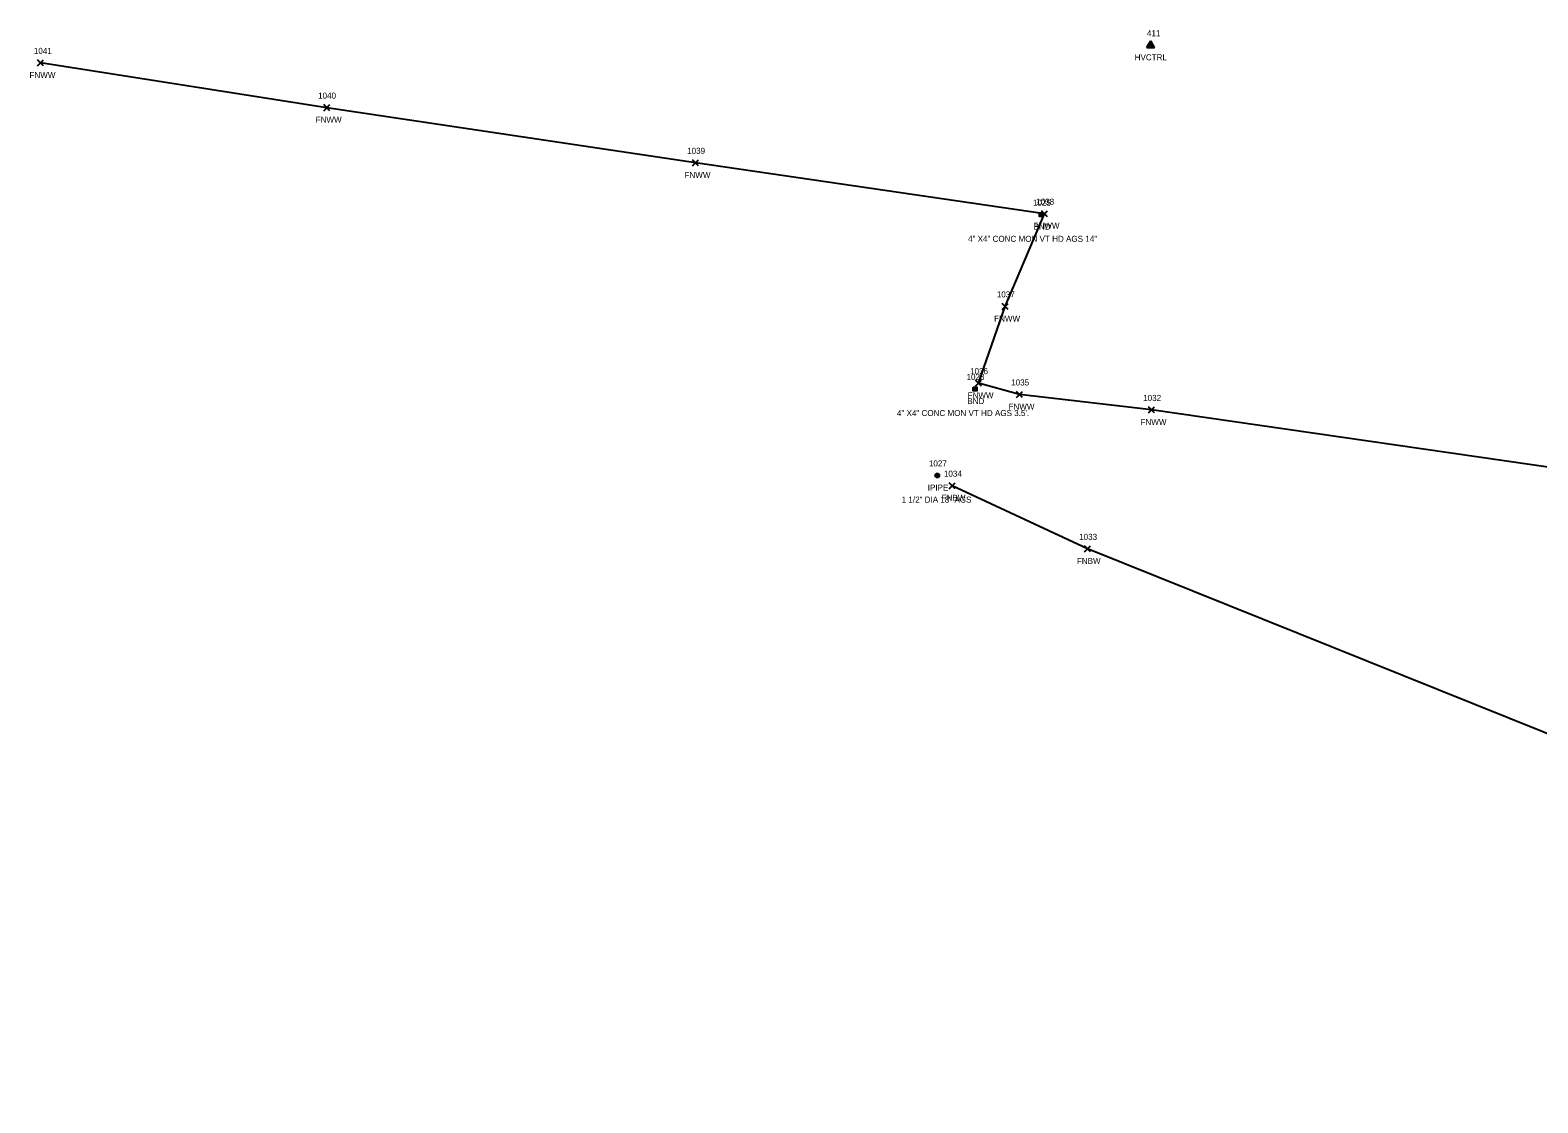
# Model space of a CAD drawing. Extents: x 1476446 to 1480467, y 706602 to 709082.
# Drawn here: x 1476446 to 1476946, y 707427 to 707782 of the extents above; entities that cross this region are included whole.
import ezdxf

# ---------------------------------------------------------------- set-up
doc = ezdxf.new("R2010")
doc.units = 0
for name, color, linetype in [('C_A', 7, 'Continuous'), ('C_I', 7, 'Continuous'), ('CPSM', 7, 'Continuous'), ('L_A', 7, 'Continuous'), ('L_I', 7, 'Continuous'), ('L_TIC', 7, 'Continuous'), ('Level 18', 7, 'Continuous'), ('LFNC', 7, 'Continuous'), ('M_A', 7, 'Continuous'), ('M_C', 7, 'Continuous'), ('M_I', 7, 'Continuous'), ('MPIP', 7, 'Continuous')]:
    doc.layers.add(name, color=color, linetype=linetype)

msp = doc.modelspace()

# ---------------------------------------------------------------- linework, layer by layer
at = {"layer": 'CPSM'}
for p, q in [((1476816.13, 707776.73), (1476817.38, 707778.9)), ((1476816.13, 707776.73), (1476817.38, 707777.45)), ((1476816.13, 707776.73), (1476818.63, 707776.73)), ((1476818.63, 707776.73), (1476817.38, 707778.9)), ((1476817.38, 707777.45), (1476817.38, 707778.9)), ((1476817.38, 707777.45), (1476817.38, 707777.45)), ((1476817.38, 707777.45), (1476818.63, 707776.73))]:
    msp.add_line(p, q, dxfattribs=at)
at = {"layer": 'L_TIC'}
for points in [[(1476447.98, 707770.58), (1476449.98, 707772.58)], [(1476449.98, 707770.58), (1476447.98, 707772.58)], [(1476542.95, 707755.73), (1476544.95, 707757.73)], [(1476544.95, 707755.73), (1476542.95, 707757.73)], [(1476665.34, 707737.41), (1476667.34, 707739.41)], [(1476667.34, 707737.41), (1476665.34, 707739.41)], [(1476781.16, 707720.55), (1476783.16, 707722.55)], [(1476783.16, 707720.55), (1476781.16, 707722.55)], [(1476768.09, 707689.76), (1476770.09, 707691.76)], [(1476770.09, 707689.76), (1476768.09, 707691.76)], [(1476759.27, 707664.31), (1476761.27, 707666.31)], [(1476761.27, 707664.31), (1476759.27, 707666.31)], [(1476772.86, 707660.56), (1476774.86, 707662.56)], [(1476774.86, 707660.56), (1476772.86, 707662.56)], [(1476816.67, 707655.43), (1476818.67, 707657.43)], [(1476818.67, 707655.43), (1476816.67, 707657.43)], [(1476750.54, 707630.28), (1476752.54, 707632.28)], [(1476752.54, 707630.28), (1476750.54, 707632.28)], [(1476795.42, 707609.33), (1476797.42, 707611.33)], [(1476797.42, 707609.33), (1476795.42, 707611.33)]]:
    msp.add_lwpolyline(points, dxfattribs=at)
at = {"layer": 'Level 18'}
for points in [[(1476780.46, 707721.85), (1476781.71, 707721.85), (1476781.71, 707720.6), (1476780.46, 707720.6)], [(1476758.43, 707664.03), (1476759.68, 707664.03), (1476759.68, 707662.78), (1476758.43, 707662.78)]]:
    msp.add_lwpolyline(points, close=True, dxfattribs=at)
for centre in [(1476781.08, 707721.22), (1476759.05, 707663.4)]:
    msp.add_circle(centre, 0.0833, dxfattribs=at)
at = {"layer": 'LFNC'}
for points in [[(1478416.61, 707432.38), (1478229.51, 707458.66), (1478087.28, 707476.81), (1477059.97, 707622.26), (1476970.61, 707634.31), (1476817.67, 707656.43), (1476773.86, 707661.56), (1476760.27, 707665.31), (1476769.09, 707690.76), (1476782.16, 707721.55), (1476666.34, 707738.41), (1476543.95, 707756.73), (1476448.98, 707771.58)], [(1479373.53, 706612.83), (1479179.17, 706689.1), (1478932.9, 706779.82), (1478858.54, 706807.19), (1478649.63, 706887.84), (1478518.06, 706938.91), (1478366.6, 707000.67), (1478164.37, 707075.29), (1476959.3, 707544.85), (1476796.42, 707610.33), (1476751.54, 707631.28)]]:
    msp.add_lwpolyline(points, dxfattribs=at)
at = {"layer": 'MPIP'}
msp.add_lwpolyline([(1476746.9, 707634.69), (1476746.56, 707635.02), (1476746.23, 707634.69), (1476746.56, 707634.36)], close=True, dxfattribs=at)
msp.add_circle((1476746.56, 707634.69), 0.667, dxfattribs=at)

# ---------------------------------------------------------------- texts
at = {"layer": 'C_A'}
msp.add_text('HVCTRL', height=2, dxfattribs=at).set_placement((1476812.07, 707772.45))
at = {"layer": 'C_I'}
msp.add_text('411', height=2, dxfattribs=at).set_placement((1476816.15, 707780.45))
at = {"layer": 'L_A'}
for s, p in [('FNWW', (1476445.33, 707766.58)), ('FNWW', (1476540.3, 707751.73)), ('FNWW', (1476662.69, 707733.41)), ('FNWW', (1476778.51, 707716.55)), ('FNWW', (1476765.44, 707685.76)), ('FNWW', (1476756.62, 707660.31)), ('FNWW', (1476770.21, 707656.56)), ('FNWW', (1476814.01, 707651.43)), ('FNBW', (1476748.02, 707626.28)), ('FNBW', (1476792.9, 707605.33))]:
    msp.add_text(s, height=2, dxfattribs=at).set_placement(p)
at = {"layer": 'L_I'}
for s, p in [('1041', (1476446.78, 707774.58)), ('1040', (1476541.1, 707759.73)), ('1039', (1476663.56, 707741.41)), ('1038', (1476779.39, 707724.55)), ('1037', (1476766.32, 707693.76)), ('1036', (1476757.45, 707668.31)), ('1035', (1476771.09, 707664.56)), ('1032', (1476814.9, 707659.43)), ('1034', (1476748.77, 707634.28)), ('1033', (1476793.65, 707613.33))]:
    msp.add_text(s, height=2, dxfattribs=at).set_placement(p)
at = {"layer": 'M_A'}
for s, p in [('BND', (1476778.57, 707716.22)), ('BND', (1476756.54, 707658.4)), ('IPIPE', (1476743.4, 707629.69))]:
    msp.add_text(s, height=2, dxfattribs=at).set_placement(p)
at = {"layer": 'M_C'}
for s, p in [('4" X4" CONC MON VT HD AGS 14"', (1476756.77, 707712.22)), ('4" X4" CONC MON VT HD AGS 3.5\'.', (1476733.19, 707654.4)), ('1 1/2" DIA 18" AGS', (1476734.75, 707625.69))]:
    msp.add_text(s, height=2, dxfattribs=at).set_placement(p)
at = {"layer": 'M_I'}
for s, p in [('1025', (1476778.31, 707724.22)), ('1028', (1476756.28, 707666.4)), ('1027', (1476743.79, 707637.69))]:
    msp.add_text(s, height=2, dxfattribs=at).set_placement(p)

doc.saveas('drawing.dxf')
